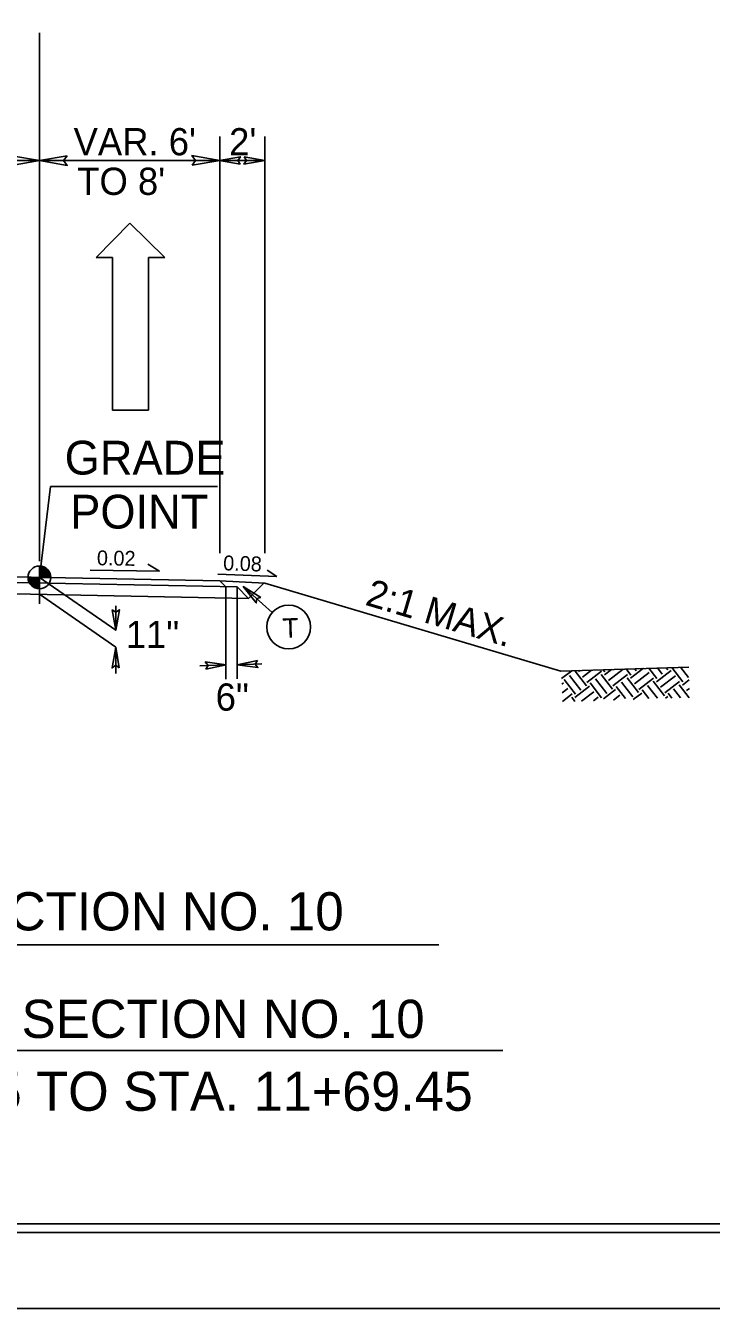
# Model space of a CAD drawing. Extents: x 3025871 to 3026431, y 707165 to 707825.
# Drawn here: x 3026209 to 3026239.4, y 707222.4 to 707279.3 of the extents above; entities that cross this region are included whole.
import ezdxf

# ---------------------------------------------------------------- set-up
doc = ezdxf.new("R2010")
doc.units = 0
for name, color, linetype in [('Old_Level_39', 7, 'Continuous'), ('Prop Drainage Structure Junction Box with Manhole CELL', 7, 'Continuous'), ('Prop Drainage Structure Junction Box with Manhole Label', 7, 'Continuous'), ('Prop Drainage Structure Junction Box with Slab Lid CELL', 7, 'Continuous'), ('Prop Drainage Structure Junction Box with Slab Lid TB 840 34 CELL', 7, 'Continuous'), ('Prop Drainage Structure Plot Symbol 20 Scale', 7, 'Continuous'), ('Prop Pavement Schedule Description CELL', 7, 'Continuous'), ('Sheet Cutting Line CELL', 7, 'Continuous'), ('Sheet Data Field CELL', 7, 'Continuous'), ('Sheet Sticker Incomplete CELL', 7, 'Continuous'), ('Sheet Typical CELL', 7, 'Continuous'), ('Typical Arrow Superelevation CELL', 7, 'Continuous'), ('Typical Curb CELL', 7, 'Continuous'), ('Typical Grade Point Symbol CELL', 7, 'Continuous'), ('Typical Shoulder Slope CELL', 7, 'Continuous'), ('Typical Terminator CELL', 7, 'Continuous'), ('Typical Text Centerline CELL', 7, 'Continuous'), ('Typical Text Grade Point CELL', 7, 'Continuous')]:
    doc.layers.add(name, color=color, linetype=linetype)

msp = doc.modelspace()

# ---------------------------------------------------------------- linework, layer by layer
at = {"layer": 'Old_Level_39'}
msp.add_lwpolyline([(3026273.948, 707384.017), (3026023.973, 707384.017), (3026023.973, 707225.752), (3026273.948, 707225.752)], close=True, dxfattribs=at)
at = {"layer": 'Prop Drainage Structure Junction Box with Manhole CELL'}
for q in [(3026219.536, 707254.567), (3026200.32, 707254.255)]:
    msp.add_line((3026218.846, 707253.884), q, dxfattribs=at)
at = {"layer": 'Prop Drainage Structure Junction Box with Manhole Label'}
msp.add_line((3026209.573, 707255.533), (3026209.573, 707278.978), dxfattribs=at)
at = {"layer": 'Prop Drainage Structure Junction Box with Slab Lid CELL'}
for p, q in [((3026209.573, 707254.82), (3026209.573, 707255.324)), ((3026209.069, 707254.82), (3026209.573, 707254.82)), ((3026209.571, 707254.317), (3026209.573, 707254.82)), ((3026209.573, 707254.82), (3026209.571, 707254.317)), ((3026210.076, 707254.82), (3026209.573, 707254.82))]:
    msp.add_line(p, q, dxfattribs=at)
for points in [[(3026209.577, 707255.324), (3026209.577, 707255.324), (3026209.577, 707254.82)], [(3026209.587, 707255.324), (3026209.587, 707254.82)], [(3026209.598, 707255.322), (3026209.597, 707254.82)], [(3026209.608, 707255.322), (3026209.607, 707254.82)], [(3026209.618, 707255.321), (3026209.617, 707254.82)], [(3026209.628, 707255.32), (3026209.628, 707254.82)], [(3026209.638, 707255.319), (3026209.638, 707254.82)], [(3026209.648, 707255.318), (3026209.648, 707254.82)], [(3026209.658, 707255.317), (3026209.658, 707254.82)], [(3026209.668, 707255.315), (3026209.668, 707254.82)], [(3026209.678, 707255.312), (3026209.678, 707254.82)], [(3026209.688, 707255.31), (3026209.688, 707254.82)], [(3026209.698, 707255.308), (3026209.698, 707254.82)], [(3026209.708, 707255.305), (3026209.708, 707254.82)], [(3026209.718, 707255.302), (3026209.718, 707254.82)], [(3026209.728, 707255.299), (3026209.728, 707254.82)], [(3026209.738, 707255.296), (3026209.738, 707254.82)], [(3026209.749, 707255.292), (3026209.748, 707254.82)], [(3026209.759, 707255.288), (3026209.758, 707254.82)], [(3026209.769, 707255.283), (3026209.769, 707254.82)], [(3026209.779, 707255.279), (3026209.779, 707254.82)], [(3026209.789, 707255.274), (3026209.789, 707254.82)], [(3026209.799, 707255.27), (3026209.799, 707254.82)], [(3026209.809, 707255.264), (3026209.809, 707254.82)], [(3026209.819, 707255.259), (3026209.819, 707254.82)], [(3026209.829, 707255.253), (3026209.829, 707254.82)], [(3026209.839, 707255.247), (3026209.839, 707254.82)], [(3026209.849, 707255.241), (3026209.849, 707254.82)], [(3026209.859, 707255.234), (3026209.859, 707254.82)], [(3026209.869, 707255.226), (3026209.869, 707254.82)], [(3026209.879, 707255.219), (3026209.879, 707254.82)], [(3026209.89, 707255.212), (3026209.889, 707254.82)], [(3026209.9, 707255.203), (3026209.899, 707254.82)], [(3026209.91, 707255.194), (3026209.909, 707254.82)], [(3026209.92, 707255.185), (3026209.92, 707254.82)], [(3026209.93, 707255.175), (3026209.93, 707254.82)], [(3026209.94, 707255.165), (3026209.94, 707254.82)], [(3026209.95, 707255.153), (3026209.95, 707254.82)], [(3026209.96, 707255.141), (3026209.96, 707254.82)], [(3026209.97, 707255.129), (3026209.97, 707254.82)], [(3026209.071, 707254.82), (3026209.071, 707254.765)], [(3026209.081, 707254.82), (3026209.081, 707254.706)], [(3026209.092, 707254.82), (3026209.091, 707254.67)], [(3026209.102, 707254.82), (3026209.102, 707254.64)], [(3026209.112, 707254.82), (3026209.112, 707254.617)], [(3026209.122, 707254.82), (3026209.122, 707254.595)], [(3026209.132, 707254.82), (3026209.132, 707254.576)], [(3026209.142, 707254.82), (3026209.142, 707254.558)], [(3026209.152, 707254.82), (3026209.152, 707254.543)], [(3026209.162, 707254.82), (3026209.162, 707254.528)], [(3026209.172, 707254.82), (3026209.172, 707254.515)], [(3026209.182, 707254.82), (3026209.182, 707254.502)], [(3026209.192, 707254.82), (3026209.192, 707254.49)], [(3026209.202, 707254.82), (3026209.202, 707254.479)], [(3026209.212, 707254.82), (3026209.212, 707254.468)], [(3026209.222, 707254.82), (3026209.222, 707254.458)], [(3026209.233, 707254.82), (3026209.232, 707254.449)], [(3026209.243, 707254.82), (3026209.242, 707254.44)], [(3026209.253, 707254.82), (3026209.253, 707254.431)], [(3026209.263, 707254.82), (3026209.263, 707254.423)], [(3026209.273, 707254.82), (3026209.273, 707254.415)], [(3026209.283, 707254.82), (3026209.283, 707254.408)], [(3026209.293, 707254.82), (3026209.293, 707254.402)], [(3026209.303, 707254.82), (3026209.303, 707254.395)], [(3026209.313, 707254.82), (3026209.313, 707254.388)], [(3026209.323, 707254.82), (3026209.323, 707254.383)], [(3026209.333, 707254.82), (3026209.333, 707254.377)], [(3026209.343, 707254.82), (3026209.343, 707254.371)], [(3026209.353, 707254.82), (3026209.353, 707254.367)], [(3026209.363, 707254.82), (3026209.363, 707254.362)], [(3026209.374, 707254.82), (3026209.373, 707254.358)], [(3026209.384, 707254.82), (3026209.383, 707254.354)], [(3026209.394, 707254.82), (3026209.393, 707254.349)], [(3026209.404, 707254.82), (3026209.404, 707254.346)], [(3026209.414, 707254.82), (3026209.414, 707254.342)], [(3026209.424, 707254.82), (3026209.424, 707254.339)], [(3026209.434, 707254.82), (3026209.434, 707254.337)], [(3026209.444, 707254.82), (3026209.444, 707254.333)], [(3026209.454, 707254.82), (3026209.454, 707254.331)], [(3026209.464, 707254.82), (3026209.464, 707254.329)], [(3026209.474, 707254.82), (3026209.474, 707254.327)], [(3026209.484, 707254.82), (3026209.484, 707254.324)], [(3026209.494, 707254.82), (3026209.494, 707254.323)], [(3026209.504, 707254.82), (3026209.504, 707254.321)], [(3026209.515, 707254.82), (3026209.514, 707254.32)], [(3026209.525, 707254.82), (3026209.524, 707254.319)], [(3026209.535, 707254.82), (3026209.534, 707254.318)], [(3026209.545, 707254.82), (3026209.545, 707254.318)], [(3026209.555, 707254.82), (3026209.555, 707254.317)], [(3026209.565, 707254.82), (3026209.565, 707254.317), (3026209.565, 707254.317)], [(3026209.98, 707255.115), (3026209.98, 707254.82)], [(3026209.99, 707255.101), (3026209.99, 707254.82)], [(3026210, 707255.085), (3026210, 707254.82)], [(3026210.01, 707255.068), (3026210.01, 707254.82)], [(3026210.02, 707255.05), (3026210.02, 707254.82)], [(3026210.03, 707255.029), (3026210.03, 707254.82)], [(3026210.04, 707255.006), (3026210.04, 707254.82)], [(3026210.051, 707254.978), (3026210.051, 707254.82)], [(3026210.061, 707254.943), (3026210.061, 707254.82)], [(3026210.071, 707254.892), (3026210.071, 707254.82)]]:
    msp.add_lwpolyline(points, dxfattribs=at)
msp.add_circle((3026209.572, 707254.82), 0.504, dxfattribs=at)
for start, end in [(359.9709, 89.9709), (179.9709, 269.9709)]:
    msp.add_arc((3026209.572, 707254.82), 0.504, start, end, dxfattribs=at)
at = {"layer": 'Prop Drainage Structure Junction Box with Slab Lid TB 840 34 CELL'}
for p, q in [((3026217.573, 707255.888), (3026217.573, 707274.385)), ((3026219.573, 707255.888), (3026219.573, 707274.385)), ((3026209.573, 707273.312), (3026199.573, 707273.312)), ((3026209.573, 707273.318), (3026219.573, 707273.318)), ((3026217.573, 707273.318), (3026219.573, 707273.32)), ((3026209.573, 707254.82), (3026212.958, 707252.471)), ((3026209.571, 707254.07), (3026212.958, 707251.72)), ((3026217.846, 707254.405), (3026217.846, 707250.307)), ((3026218.346, 707254.395), (3026218.346, 707250.317)), ((3026212.958, 707252.471), (3026212.958, 707253.564)), ((3026218.346, 707250.941), (3026219.437, 707250.984)), ((3026191.853, 707238.522), (3026227.293, 707238.522)), ((3026189.627, 707233.821), (3026230.131, 707233.821))]:
    msp.add_line(p, q, dxfattribs=at)
at = {"layer": 'Prop Drainage Structure Plot Symbol 20 Scale'}
msp.add_line((3026209.573, 707254.82), (3026210.065, 707258.856), dxfattribs=at)
at = {"layer": 'Prop Pavement Schedule Description CELL'}
for p, q in [((3026218.346, 707254.395), (3026200.815, 707254.745)), ((3026217.573, 707254.66), (3026201.573, 707254.98)), ((3026217.573, 707254.66), (3026217.846, 707254.405)), ((3026218.346, 707254.395), (3026218.846, 707253.884))]:
    msp.add_line(p, q, dxfattribs=at)
at = {"layer": 'Sheet Cutting Line CELL'}
msp.add_lwpolyline([(3026272.073, 707383.635), (3026047.073, 707383.635), (3026047.073, 707226.135), (3026272.073, 707226.135)], close=True, dxfattribs=at)
at = {"layer": 'Sheet Data Field CELL'}
for p, q in [((3026212.09, 707269.015), (3026213.589, 707270.538)), ((3026213.589, 707270.538), (3026215.136, 707269.015)), ((3026212.815, 707269.015), (3026212.09, 707269.015)), ((3026212.815, 707262.245), (3026212.815, 707269.015)), ((3026215.136, 707269.015), (3026214.411, 707269.015)), ((3026214.411, 707269.015), (3026214.411, 707262.245)), ((3026214.411, 707262.245), (3026212.815, 707262.245))]:
    msp.add_line(p, q, dxfattribs=at)
at = {"layer": 'Sheet Sticker Incomplete CELL'}
for p, q in [((3026214.9, 707255.093), (3026211.832, 707255.147)), ((3026214.9, 707255.093), (3026214.384, 707255.403)), ((3026220.114, 707254.866), (3026219.678, 707255.139)), ((3026220.114, 707254.866), (3026217.494, 707254.958))]:
    msp.add_line(p, q, dxfattribs=at)
at = {"layer": 'Sheet Typical CELL'}
msp.add_line((3026217.573, 707254.66), (3026219.577, 707254.565), dxfattribs=at)
at = {"layer": 'Typical Curb CELL'}
msp.add_line((3026209.571, 707254.317), (3026209.571, 707253.648), dxfattribs=at)
at = {"layer": 'Typical Grade Point Symbol CELL'}
for p, q in [((3026219.906, 707253.268), (3026218.617, 707254.414)), ((3026212.959, 707250.549), (3026212.958, 707251.72)), ((3026216.685, 707250.894), (3026217.855, 707250.941))]:
    msp.add_line(p, q, dxfattribs=at)
msp.add_circle((3026220.631, 707252.621), 0.972, dxfattribs=at)
at = {"layer": 'Typical Shoulder Slope CELL'}
msp.add_line((3026210.065, 707258.856), (3026217.478, 707258.854), dxfattribs=at)
at = {"layer": 'Typical Terminator CELL'}
msp.add_lwpolyline([(3026274.623, 707387.385), (3026022.023, 707387.385), (3026022.023, 707222.385), (3026274.623, 707222.385)], close=True, dxfattribs=at)
at = {"layer": 'Typical Text Centerline CELL'}
for points in [[(3026208.348, 707273.523), (3026209.573, 707273.312), (3026208.341, 707273.094), (3026208.497, 707273.312)], [(3026210.798, 707273.529), (3026209.573, 707273.318), (3026210.805, 707273.1), (3026210.648, 707273.318)], [(3026216.348, 707273.107), (3026217.573, 707273.318), (3026216.341, 707273.536), (3026216.497, 707273.318)], [(3026218.483, 707273.161), (3026217.565, 707273.32), (3026218.489, 707273.483), (3026218.371, 707273.32)], [(3026218.655, 707273.478), (3026219.573, 707273.32), (3026218.649, 707273.156), (3026218.767, 707273.32)], [(3026219.401, 707253.926), (3026218.617, 707254.414), (3026219.193, 707253.685), (3026219.214, 707253.883)], [(3026212.801, 707253.381), (3026212.958, 707252.471), (3026213.12, 707253.386), (3026212.958, 707253.27)], [(3026213.116, 707250.811), (3026212.958, 707251.72), (3026212.797, 707250.806), (3026212.959, 707250.922)], [(3026216.952, 707250.748), (3026217.855, 707250.941), (3026216.935, 707251.066), (3026217.057, 707250.909)], [(3026219.249, 707251.134), (3026218.346, 707250.941), (3026219.266, 707250.816), (3026219.144, 707250.973)]]:
    msp.add_lwpolyline(points, close=True, dxfattribs=at)
at = {"layer": 'Typical Text Grade Point CELL'}
for p, q in [((3026219.577, 707254.565), (3026232.711, 707250.658)), ((3026232.711, 707250.658), (3026238.393, 707250.843)), ((3026232.711, 707250.658), (3026238.393, 707250.843)), ((3026232.744, 707250.33), (3026233.192, 707250.675)), ((3026232.744, 707250.33), (3026233.192, 707250.675)), ((3026233.845, 707250.008), (3026233.343, 707250.661)), ((3026233.845, 707250.008), (3026233.343, 707250.661)), ((3026233.487, 707250.642), (3026233.546, 707250.687)), ((3026233.487, 707250.642), (3026233.546, 707250.687)), ((3026233.675, 707250.397), (3026234.077, 707250.706)), ((3026233.675, 707250.397), (3026234.077, 707250.706)), ((3026233.864, 707250.153), (3026234.516, 707250.655)), ((3026233.864, 707250.153), (3026234.516, 707250.655)), ((3026234.66, 707250.636), (3026234.592, 707250.724)), ((3026234.66, 707250.636), (3026234.592, 707250.724)), ((3026234.642, 707250.492), (3026234.961, 707250.738)), ((3026234.642, 707250.492), (3026234.961, 707250.738)), ((3026234.83, 707250.247), (3026235.482, 707250.749)), ((3026234.83, 707250.247), (3026235.482, 707250.749)), ((3026235.815, 707250.485), (3026235.603, 707250.76)), ((3026235.815, 707250.485), (3026235.603, 707250.76)), ((3026235.796, 707250.341), (3026236.377, 707250.788)), ((3026235.796, 707250.341), (3026236.377, 707250.788)), ((3026236.059, 707250.673), (3026235.982, 707250.774)), ((3026236.059, 707250.673), (3026235.982, 707250.774)), ((3026235.984, 707250.096), (3026236.636, 707250.598)), ((3026235.984, 707250.096), (3026236.636, 707250.598)), ((3026236.969, 707250.335), (3026236.622, 707250.786)), ((3026236.969, 707250.335), (3026236.622, 707250.786)), ((3026236.95, 707250.19), (3026237.602, 707250.692)), ((3026236.95, 707250.19), (3026237.602, 707250.692)), ((3026237.213, 707250.523), (3026236.993, 707250.81)), ((3026237.213, 707250.523), (3026236.993, 707250.81)), ((3026237.458, 707250.711), (3026237.382, 707250.81)), ((3026237.458, 707250.711), (3026237.382, 707250.81)), ((3026238.123, 707250.184), (3026237.635, 707250.819)), ((3026238.123, 707250.184), (3026237.635, 707250.819)), ((3026238.368, 707250.372), (3026238.015, 707250.831)), ((3026238.368, 707250.372), (3026238.015, 707250.831)), ((3026232.752, 707250.076), (3026232.835, 707250.14)), ((3026232.752, 707250.076), (3026232.835, 707250.14)), ((3026233.356, 707249.632), (3026232.854, 707250.284)), ((3026233.356, 707249.632), (3026232.854, 707250.284)), ((3026233.6, 707249.82), (3026233.098, 707250.473)), ((3026233.6, 707249.82), (3026233.098, 707250.473)), ((3026234.51, 707249.482), (3026234.008, 707250.134)), ((3026234.51, 707249.482), (3026234.008, 707250.134)), ((3026234.754, 707249.67), (3026234.253, 707250.322)), ((3026234.754, 707249.67), (3026234.253, 707250.322)), ((3026234.999, 707249.858), (3026234.497, 707250.51)), ((3026234.999, 707249.858), (3026234.497, 707250.51)), ((3026235.018, 707250.002), (3026235.67, 707250.504)), ((3026235.018, 707250.002), (3026235.67, 707250.504)), ((3026235.909, 707249.519), (3026235.407, 707250.172)), ((3026235.909, 707249.519), (3026235.407, 707250.172)), ((3026236.153, 707249.707), (3026235.651, 707250.36)), ((3026236.153, 707249.707), (3026235.651, 707250.36)), ((3026236.172, 707249.852), (3026236.825, 707250.354)), ((3026236.172, 707249.852), (3026236.825, 707250.354)), ((3026236.995, 707249.457), (3026236.561, 707250.021)), ((3026236.995, 707249.457), (3026236.561, 707250.021)), ((3026237.308, 707249.557), (3026236.806, 707250.209)), ((3026237.308, 707249.557), (3026236.806, 707250.209)), ((3026237.138, 707249.946), (3026237.791, 707250.448)), ((3026237.138, 707249.946), (3026237.791, 707250.448)), ((3026237.326, 707249.701), (3026237.979, 707250.203)), ((3026237.326, 707249.701), (3026237.979, 707250.203)), ((3026238.409, 707249.475), (3026237.96, 707250.059)), ((3026238.409, 707249.475), (3026237.96, 707250.059)), ((3026238.104, 707250.04), (3026238.411, 707250.276)), ((3026238.104, 707250.04), (3026238.411, 707250.276)), ((3026232.764, 707249.696), (3026233.023, 707249.896)), ((3026232.764, 707249.696), (3026233.023, 707249.896)), ((3026232.777, 707249.317), (3026233.211, 707249.651)), ((3026232.777, 707249.317), (3026233.211, 707249.651)), ((3026233.338, 707249.318), (3026233.192, 707249.507)), ((3026233.338, 707249.318), (3026233.192, 707249.507)), ((3026233.337, 707249.488), (3026233.989, 707249.99)), ((3026233.337, 707249.488), (3026233.989, 707249.99)), ((3026233.634, 707249.327), (3026234.177, 707249.745)), ((3026233.634, 707249.327), (3026234.177, 707249.745)), ((3026234.163, 707249.345), (3026234.366, 707249.5)), ((3026234.163, 707249.345), (3026234.366, 707249.5)), ((3026234.608, 707249.427), (3026235.143, 707249.839)), ((3026234.608, 707249.427), (3026235.143, 707249.839)), ((3026235.044, 707249.373), (3026235.332, 707249.595)), ((3026235.044, 707249.373), (3026235.332, 707249.595)), ((3026235.581, 707249.439), (3026235.162, 707249.983)), ((3026235.581, 707249.439), (3026235.162, 707249.983)), ((3026235.925, 707249.402), (3026236.298, 707249.689)), ((3026235.925, 707249.402), (3026236.298, 707249.689)), ((3026236.609, 707249.452), (3026236.316, 707249.833)), ((3026236.609, 707249.452), (3026236.316, 707249.833)), ((3026237.352, 707249.461), (3026237.452, 707249.538)), ((3026237.352, 707249.461), (3026237.452, 707249.538)), ((3026237.638, 707249.465), (3026237.471, 707249.682)), ((3026237.638, 707249.465), (3026237.471, 707249.682)), ((3026238.024, 707249.47), (3026237.715, 707249.871)), ((3026238.024, 707249.47), (3026237.715, 707249.871)), ((3026238.292, 707249.795), (3026238.424, 707249.896)), ((3026238.292, 707249.795), (3026238.424, 707249.896))]:
    msp.add_line(p, q, dxfattribs=at)

# ---------------------------------------------------------------- texts
at = {"layer": 'Prop Drainage Structure Junction Box with Slab Lid TB 840 34 CELL'}
for s, height, p in [("VAR. 6'", 1.2089, (3026211.09, 707273.549)), ("2'", 1.2089, (3026217.992, 707273.545)), ("TO 8'", 1.2089, (3026211.251, 707271.792)), ('11"', 1.2089, (3026213.404, 707251.682)), ('USE TYPICAL SECTION NO. 10', 1.69489, (3026193.416, 707234.383)), ('-DR2- STA. 10+41.45 TO STA. 11+69.45', 1.73151, (3026186.461, 707231.152))]:
    msp.add_text(s, height=height, dxfattribs=at).set_placement(p)
for s, height, rotation, p in [('6"', 1.2089, 0.0026, (3026217.394, 707248.907)), ('TYPICAL SECTION NO. 10', 1.69489, 360, (3026195.115, 707239.155))]:
    msp.add_text(s, height=height, rotation=rotation, dxfattribs=at).set_placement(p)
at = {"layer": 'Sheet Sticker Incomplete CELL'}
for s, rotation, p in [('0.02', 358.9809, (3026212.12, 707255.36)), ('0.08', 357.9884, (3026217.718, 707255.139))]:
    msp.add_text(s, height=0.6583, rotation=rotation, dxfattribs=at).set_placement(p)
at = {"layer": 'Typical Arrow Superelevation CELL'}
msp.add_text('T', height=0.87, rotation=1.868, dxfattribs=at).set_placement((3026220.374, 707252.128))
at = {"layer": 'Typical Shoulder Slope CELL'}
for s, p in [('GRADE', (3026210.694, 707259.383)), ('POINT', (3026210.94, 707256.987))]:
    msp.add_text(s, height=1.5, rotation=359.9804, dxfattribs=at).set_placement(p)
at = {"layer": 'Typical Text Grade Point CELL'}
msp.add_text('2:1 MAX.', height=1.2089, rotation=343.433, dxfattribs=at).set_placement((3026223.984, 707253.612))

doc.saveas('drawing.dxf')
